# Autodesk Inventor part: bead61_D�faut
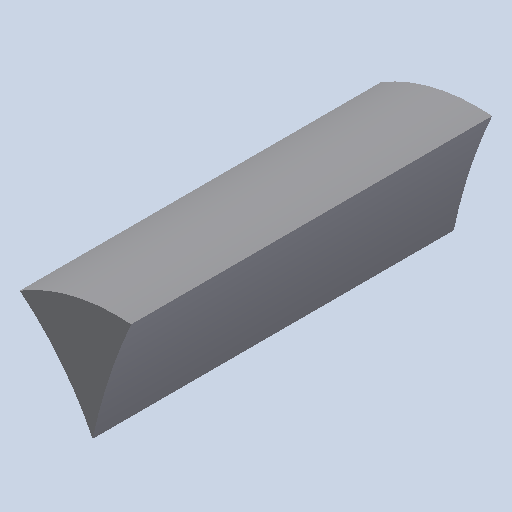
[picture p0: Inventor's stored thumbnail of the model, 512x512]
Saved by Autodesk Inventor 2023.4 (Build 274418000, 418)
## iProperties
Created: 2011-01
Part Number: bead61_D�faut
Document SubType Name: Modeling
Designer: eric
Density: 1 g/cm^3
Mass: 0.0459425 g
Surface Area: 1.08675 cm^2
Volume: 0.0459425 cm^3
Material: Générique
Appearance: Par défaut
Author: eric
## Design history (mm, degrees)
feature "Base1"
node "Corps solides"
node "Corps surfaciques"
node "Solide1"
